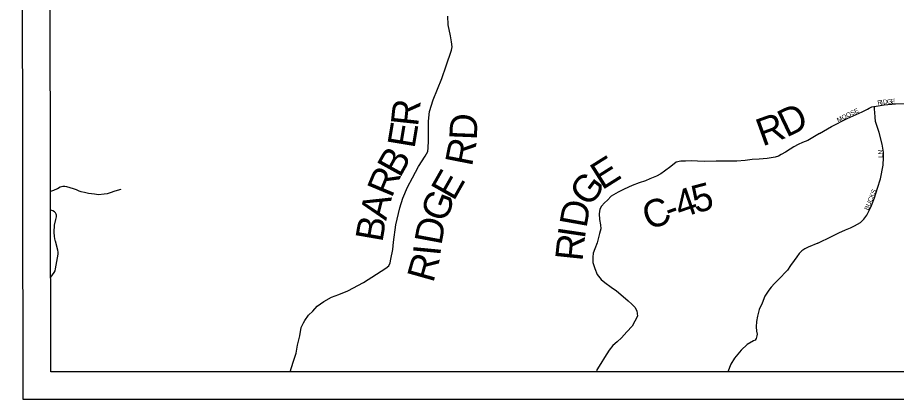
# Model space of a CAD drawing. Extents: x -15 to 405, y -40 to 87.
# Drawn here: x -14.941 to -13.026, y 34.004 to 34.837 of the extents above; entities that cross this region are included whole.
import ezdxf

# ---------------------------------------------------------------- set-up
doc = ezdxf.new("R2010")
doc.units = 0
for name, color, linetype in [('GM_P_State_Location', 7, 'Continuous'), ('GM_X_Airport_Text_Class_2', 7, 'Continuous'), ('GM_X_City_Street_Text', 7, 'Continuous'), ('GM_X_Major_River', 7, 'Continuous'), ('GM_X_Minor_Lake', 7, 'Continuous'), ('GM_X_State_Location', 7, 'Continuous'), ('GM_X_Township_Text', 7, 'Continuous')]:
    doc.layers.add(name, color=color, linetype=linetype)

msp = doc.modelspace()

# ---------------------------------------------------------------- linework, layer by layer
at = {"layer": 'GM_P_State_Location'}
for points in [[(-14.8692, 34.4583), (-14.8625, 34.4608), (-14.8541, 34.4641), (-14.8485, 34.4679), (-14.8456, 34.4691), (-14.8425, 34.4696), (-14.8386, 34.4695), (-14.8349, 34.4689), (-14.8204, 34.4647), (-14.8135, 34.4624), (-14.8079, 34.4596), (-14.8034, 34.4581), (-14.7959, 34.4561), (-14.7865, 34.454), (-14.774, 34.4525), (-14.7648, 34.4515), (-14.7524, 34.4525), (-14.7457, 34.4537), (-14.7392, 34.4555), (-14.7288, 34.4593), (-14.716, 34.4627)], [(-13.1972, 34.3455), (-13.2182, 34.3363), (-13.2254, 34.3328), (-13.2321, 34.3285), (-13.2379, 34.323), (-13.243, 34.3157), (-13.249, 34.3072), (-13.2573, 34.2967), (-13.2636, 34.2866), (-13.2699, 34.2797), (-13.2766, 34.2728), (-13.2858, 34.2631), (-13.2921, 34.257), (-13.2992, 34.2489), (-13.3044, 34.2424), (-13.3127, 34.2295), (-13.3185, 34.2141), (-13.3252, 34.2004), (-13.3286, 34.1859), (-13.3309, 34.1747), (-13.3319, 34.163), (-13.331, 34.1534), (-13.3297, 34.147), (-13.3305, 34.143), (-13.3316, 34.1374), (-13.334, 34.1337), (-13.3376, 34.1321), (-13.3511, 34.1243), (-13.3646, 34.1121), (-13.3793, 34.0947), (-13.3872, 34.0814), (-13.3936, 34.0644)]]:
    msp.add_lwpolyline(points, dxfattribs=at)
at = {"layer": 'GM_X_City_Street_Text'}
for points in [[(-13.1937, 34.5841), (-13.1676, 34.5994), (-13.1332, 34.6168), (-13.1008, 34.6318), (-13.0892, 34.6375), (-13.0852, 34.6399), (-13.0796, 34.6424), (-13.0756, 34.6432), (-13.0742, 34.6434), (-13.0704, 34.644), (-13.0527, 34.6465), (-13.0279, 34.6487), (-13.0074, 34.6496)], [(-13.1972, 34.3455), (-13.1678, 34.3599), (-13.1515, 34.3679), (-13.1368, 34.3746), (-13.1265, 34.3785), (-13.1177, 34.3827), (-13.111, 34.3863), (-13.1043, 34.3906), (-13.0971, 34.3973), (-13.0906, 34.4064), (-13.0852, 34.4163), (-13.0806, 34.4276), (-13.0741, 34.4438), (-13.0674, 34.4652), (-13.061, 34.4858), (-13.0549, 34.5152), (-13.054, 34.532), (-13.0543, 34.5436), (-13.0571, 34.5612), (-13.0641, 34.5867), (-13.0688, 34.6015), (-13.0714, 34.6106), (-13.0728, 34.6198), (-13.0734, 34.6298), (-13.0736, 34.6374), (-13.0742, 34.6434)]]:
    msp.add_lwpolyline(points, dxfattribs=at)
at = {"layer": 'GM_X_Major_River'}
msp.add_lwpolyline([(-14.8692, 34.2709), (-14.8618, 34.2813), (-14.8598, 34.2852), (-14.8588, 34.2892), (-14.8531, 34.3213), (-14.8528, 34.3256), (-14.8535, 34.3299), (-14.8591, 34.3499), (-14.8592, 34.3509), (-14.8609, 34.3594), (-14.8618, 34.3693), (-14.8613, 34.3841), (-14.8582, 34.3965), (-14.8566, 34.4026), (-14.8566, 34.4059), (-14.8573, 34.4087), (-14.8587, 34.4114), (-14.8608, 34.4136), (-14.8644, 34.4159), (-14.8687, 34.4173), (-14.8692, 34.4174)], dxfattribs=at)
at = {"layer": 'GM_X_State_Location'}
for p, q in [((-14.8692, 34.0644), (-14.8813, 42.1225)), ((-5.8735, 34.0644), (-14.8692, 34.0644))]:
    msp.add_line(p, q, dxfattribs=at)
msp.add_lwpolyline([(-14.9291, 34.0044), (-14.9414, 42.1825), (-5.8257, 42.1825), (-5.8134, 34.0044)], close=True, dxfattribs=at)
at = {"layer": 'GM_X_Township_Text'}
for points in [[(-14.3471, 34.0644), (-14.3405, 34.0859), (-14.3344, 34.1055), (-14.3315, 34.1227), (-14.3262, 34.1432), (-14.3237, 34.1612), (-14.318, 34.1716), (-14.3152, 34.1768), (-14.3075, 34.188), (-14.2982, 34.1972), (-14.2886, 34.2075), (-14.2741, 34.2179), (-14.2572, 34.2274), (-14.2415, 34.233), (-14.2214, 34.2413), (-14.1876, 34.2596), (-14.1591, 34.2779), (-14.139, 34.2906), (-14.1321, 34.2958), (-14.1297, 34.3022), (-14.1278, 34.3106), (-14.1235, 34.3314), (-14.1219, 34.3475), (-14.1169, 34.3855), (-14.1083, 34.4224), (-14.1018, 34.4436), (-14.092, 34.4672), (-14.0811, 34.4876), (-14.0678, 34.512), (-14.0532, 34.5352), (-14.0475, 34.5452), (-14.0467, 34.5528), (-14.0458, 34.5681), (-14.0461, 34.5885), (-14.0456, 34.6114), (-14.0435, 34.6326), (-14.0358, 34.6579), (-14.0261, 34.6811), (-14.0171, 34.7039), (-14.0074, 34.7315), (-13.996, 34.7663), (-13.9944, 34.7732), (-13.9955, 34.784), (-13.9983, 34.7972), (-14.003, 34.8213), (-14.0041, 34.8402)], [(-13.1937, 34.5841), (-13.2046, 34.5781), (-13.2191, 34.5694), (-13.2307, 34.5646), (-13.24, 34.5602), (-13.25, 34.5555), (-13.2577, 34.5503), (-13.2677, 34.5435), (-13.277, 34.5384), (-13.2834, 34.5348), (-13.2902, 34.5324), (-13.3075, 34.5301), (-13.3255, 34.5286), (-13.3404, 34.5275), (-13.3561, 34.5252), (-13.3737, 34.524), (-13.3906, 34.5241), (-13.419, 34.5239), (-13.4439, 34.5236), (-13.4596, 34.5237), (-13.4728, 34.5246), (-13.486, 34.5242), (-13.4961, 34.5239), (-13.5061, 34.5215), (-13.5178, 34.5124), (-13.5315, 34.502), (-13.5399, 34.496), (-13.5492, 34.4913), (-13.5636, 34.4857), (-13.5729, 34.4814), (-13.5869, 34.477), (-13.6022, 34.4711), (-13.6195, 34.4632), (-13.6328, 34.4564), (-13.6476, 34.4473), (-13.6557, 34.4389), (-13.6626, 34.4329), (-13.6686, 34.4261), (-13.6726, 34.4193), (-13.6739, 34.4089), (-13.6731, 34.3965), (-13.6712, 34.3848), (-13.6704, 34.3764), (-13.6729, 34.3664), (-13.6782, 34.3459), (-13.6835, 34.3331), (-13.6867, 34.3235), (-13.688, 34.3143), (-13.6876, 34.3027), (-13.6833, 34.2902), (-13.6785, 34.2766), (-13.6693, 34.2657), (-13.6617, 34.2592), (-13.6481, 34.2495), (-13.6365, 34.2414), (-13.6218, 34.2289), (-13.6106, 34.2197), (-13.603, 34.2124), (-13.5962, 34.2059), (-13.5922, 34.1975), (-13.5903, 34.1859), (-13.6024, 34.1639), (-13.6137, 34.1519), (-13.6254, 34.1387), (-13.635, 34.1299), (-13.6439, 34.1224), (-13.6524, 34.112), (-13.6621, 34.0956), (-13.6706, 34.0828), (-13.6787, 34.0688), (-13.6801, 34.0644)]]:
    msp.add_lwpolyline(points, dxfattribs=at)

# ---------------------------------------------------------------- texts
at = {"layer": 'GM_X_Airport_Text_Class_2'}
for s, rotation, p in [('R', 5.1549, (-13.0672, 34.6467)), ('I', 5.1561, (-13.0593, 34.6475)), ('D', 5.1548, (-13.0549, 34.6479)), ('G', 5.143, (-13.0462, 34.6486)), ('E', 5.1696, (-13.0374, 34.6494)), ('MOOSE', 26.0508, (-13.1532, 34.6087)), ('N', 94.1807, (-13.0557, 34.5392)), ('L', 90.7104, (-13.0556, 34.5315)), ('BUCKS', 68.1969, (-13.0872, 34.416))]:
    msp.add_text(s, height=0.01, rotation=rotation, dxfattribs=at).set_placement(p)
at = {"layer": 'GM_X_Minor_Lake'}
for s, rotation, p in [('R', 83.9353, (-14.0687, 34.5983)), ('D', 25.6166, (-13.2659, 34.575)), ('D', 87.6806, (-13.9407, 34.5692)), ('R', 19.9137, (-13.3181, 34.5558)), ('E', 80.5478, (-14.0766, 34.5502)), ('R', 78.8662, (-13.9514, 34.5108)), ('B', 60.9154, (-14.108, 34.486)), ('E', 32.1839, (-13.6676, 34.4601)), ('R', 67.297, (-14.1262, 34.4421)), ('E', 60.438, (-13.9909, 34.4353)), ('G', 52.6391, (-13.6955, 34.4219)), ('5', 14.8087, (-13.4635, 34.41)), ('G', 68.5422, (-14.0092, 34.3882)), ('4', 19.0192, (-13.4974, 34.3983)), ('A', 75.8727, (-14.1383, 34.3932)), ('D', 79.8496, (-13.7018, 34.3768)), ('C', 20.2879, (-13.5664, 34.3729)), ('-', 20.0298, (-13.5203, 34.39)), ('B', 80.1668, (-14.1465, 34.3458)), ('D', 79.4866, (-14.018, 34.3392)), ('R', 84.0292, (-13.7104, 34.3045)), ('I', 81.563, (-13.7054, 34.3529)), ('I', 84.4586, (-14.0202, 34.316)), ('R', 74.217, (-14.0358, 34.2571))]:
    msp.add_text(s, height=0.06, rotation=rotation, dxfattribs=at).set_placement(p)

doc.saveas('drawing.dxf')
